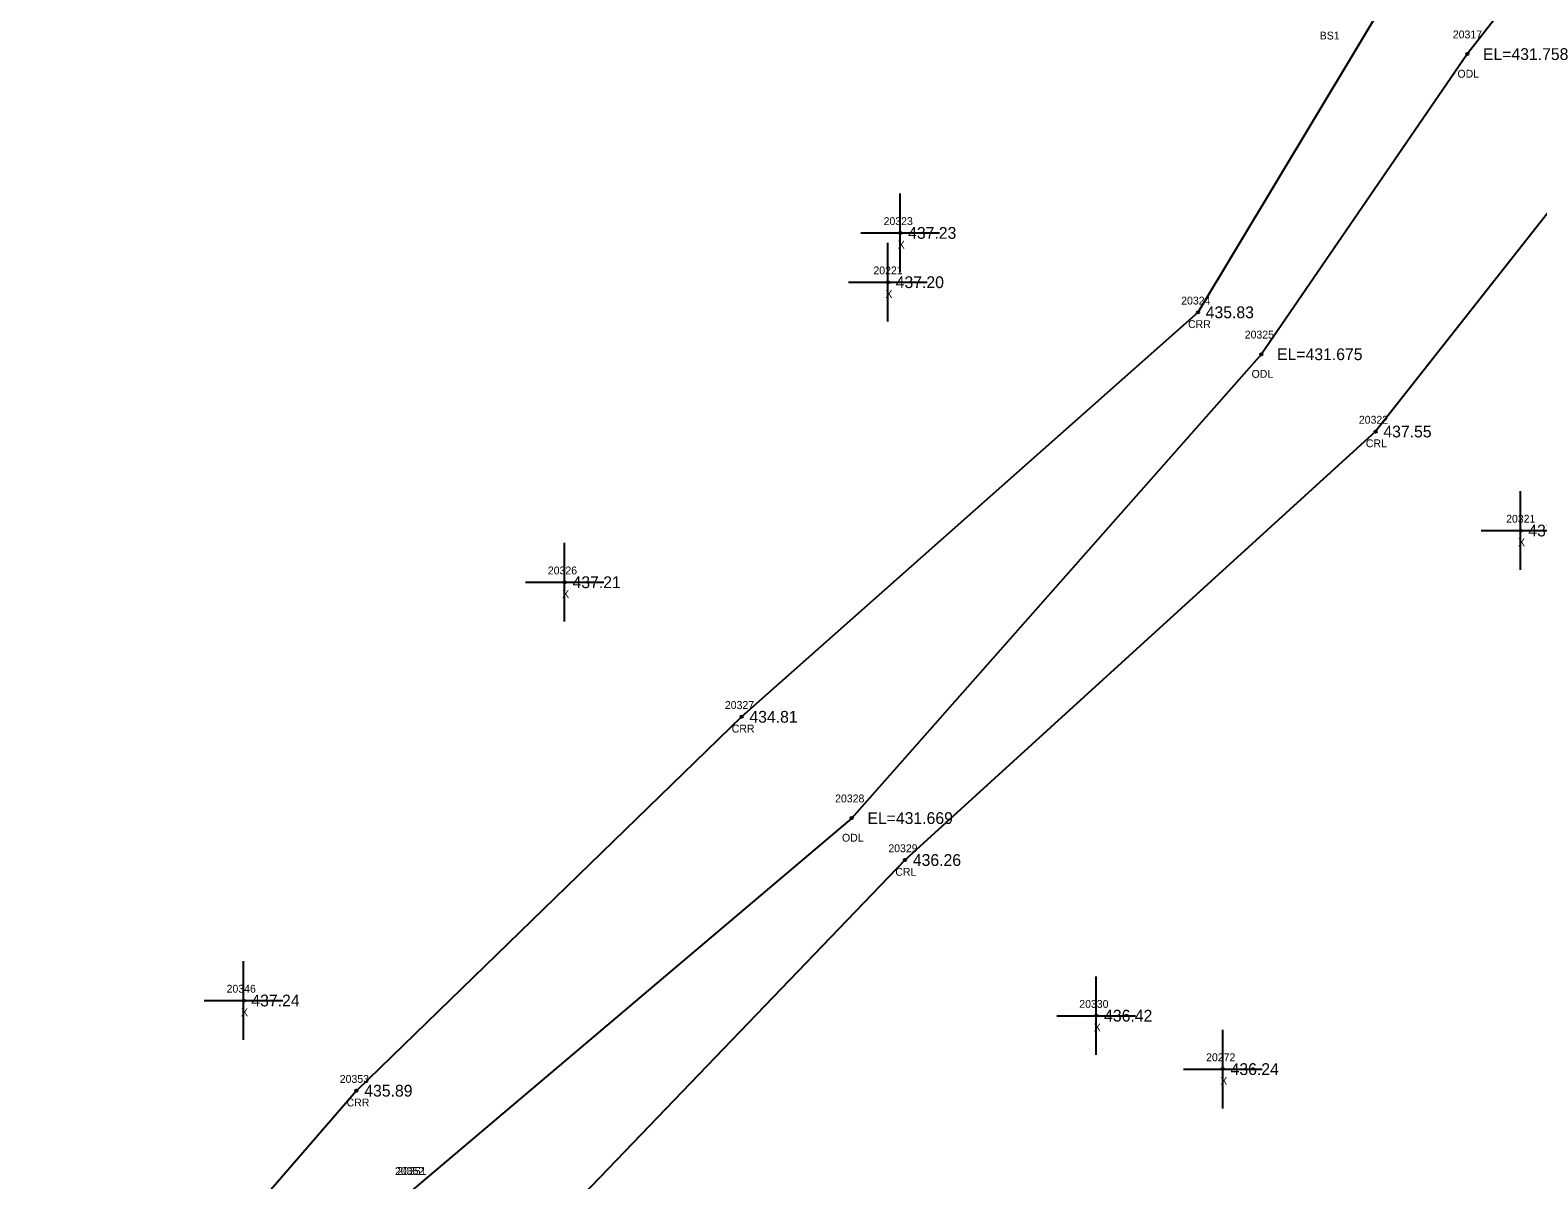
# Model space of a CAD drawing. Extents: x 1797709 to 1799052, y 896018 to 896955.
# Drawn here: x 1798186.8 to 1798378.7, y 896328.3 to 896474.6 of the extents above; entities that cross this region are included whole.
import ezdxf

# ---------------------------------------------------------------- set-up
doc = ezdxf.new("R2010")
doc.units = 0
for name, color, linetype in [('RD_DTM_BkLn_txCode', 7, 'Continuous'), ('RD_EX_H2O', 7, 'Continuous'), ('RD_EX_H2O_txCode', 7, 'Continuous'), ('RD_EX_Misc', 7, 'Continuous'), ('RD_EX_Misc_txCode', 7, 'Continuous'), ('RD_EX_TX_H2O_ELEV', 7, 'Continuous'), ('RD_EX_TX_Misc_ELEV', 7, 'Continuous'), ('RD_SMD_Locator', 7, 'Continuous')]:
    doc.layers.add(name, color=color, linetype=linetype)

msp = doc.modelspace()

# ---------------------------------------------------------------- linework, layer by layer
at = {"layer": 'RD_EX_H2O'}
for points in [[(1798652.43, 896917.58), (1798601.94, 896827.15), (1798558.78, 896718.92), (1798516.66, 896628.32), (1798463.08, 896540.21), (1798439.21, 896521.86), (1798389.85, 896497.35), (1798369.72, 896471.55), (1798343.52, 896433.35), (1798291.39, 896374.31), (1798235.39, 896326.89), (1798184.99, 896269.63), (1798095.18, 896198.01), (1798023.89, 896139.85)], [(1798502.61, 896635.66), (1798452.16, 896551.79), (1798380.86, 896504.02), (1798360.17, 896479.84), (1798335.44, 896438.68), (1798277.37, 896387.2), (1798228.36, 896339.61), (1798175.66, 896278.7), (1798083.83, 896204.11), (1798020.11, 896146.19)], [(1798443.56, 896510.19), (1798406.44, 896491.18), (1798387.57, 896460.96), (1798358.05, 896423.51), (1798298.17, 896368.97), (1798249.86, 896318.72)]]:
    msp.add_lwpolyline(points, dxfattribs=at)
at = {"layer": 'RD_EX_Misc'}
for p, q in [((1798297.57, 896443.79), (1798297.57, 896453.79)), ((1798292.57, 896448.79), (1798302.57, 896448.79)), ((1798295.99, 896437.52), (1798295.99, 896447.52)), ((1798290.99, 896442.52), (1798300.99, 896442.52)), ((1798376.5, 896405.91), (1798376.5, 896415.91)), ((1798371.5, 896410.91), (1798381.5, 896410.91)), ((1798254.86, 896399.33), (1798254.86, 896409.33)), ((1798249.86, 896404.33), (1798259.86, 896404.33)), ((1798213.99, 896346.09), (1798213.99, 896356.09)), ((1798322.51, 896344.16), (1798322.51, 896354.16)), ((1798208.99, 896351.09), (1798218.99, 896351.09)), ((1798317.51, 896349.16), (1798327.51, 896349.16)), ((1798338.61, 896337.36), (1798338.61, 896347.36)), ((1798333.61, 896342.36), (1798343.61, 896342.36))]:
    msp.add_line(p, q, dxfattribs=at)
at = {"layer": 'RD_SMD_Locator'}
for centre in [(1798369.72, 896471.55), (1798297.57, 896448.79), (1798295.99, 896442.52), (1798335.44, 896438.68), (1798343.52, 896433.35), (1798358.05, 896423.51), (1798376.5, 896410.91), (1798254.86, 896404.33), (1798277.37, 896387.2), (1798291.39, 896374.31), (1798298.17, 896368.97), (1798213.99, 896351.09), (1798322.51, 896349.16), (1798338.61, 896342.36), (1798228.36, 896339.61)]:
    msp.add_circle(centre, 0.15, dxfattribs=at)

# ---------------------------------------------------------------- texts
at = {"layer": 'RD_DTM_BkLn_txCode'}
msp.add_text('BS1', height=1, dxfattribs=at).set_placement((1798350.95, 896473.41))
at = {"layer": 'RD_EX_H2O_txCode'}
for s, p in [('20317', (1798367.89, 896473.55)), ('ODL', (1798368.48, 896468.55)), ('20324', (1798333.32, 896439.68)), ('CRR', (1798334.19, 896436.68)), ('20325', (1798341.41, 896435.35)), ('ODL', (1798342.28, 896430.35)), ('20322', (1798355.93, 896424.51)), ('CRL', (1798356.82, 896421.51)), ('20327', (1798275.25, 896388.2)), ('CRR', (1798276.12, 896385.2)), ('20328', (1798289.28, 896376.31)), ('ODL', (1798290.15, 896371.31)), ('20329', (1798296.05, 896369.97)), ('CRL', (1798296.94, 896366.97)), ('20353', (1798226.24, 896340.61)), ('CRR', (1798227.11, 896337.61)), ('20352', (1798233.27, 896328.89)), ('20351', (1798233.55, 896328.89))]:
    msp.add_text(s, height=1, dxfattribs=at).set_placement(p)
at = {"layer": 'RD_EX_Misc_txCode'}
for s, p in [('20323', (1798295.45, 896449.79)), ('X', (1798297.25, 896446.79)), ('20221', (1798294.15, 896443.52)), ('X', (1798295.67, 896440.52)), ('20321', (1798374.67, 896411.91)), ('X', (1798376.19, 896408.91)), ('20326', (1798252.72, 896405.33)), ('X', (1798254.54, 896402.33)), ('20346', (1798211.84, 896352.09)), ('20330', (1798320.35, 896350.16)), ('X', (1798213.67, 896349.09)), ('X', (1798322.19, 896347.16)), ('20272', (1798336.49, 896343.36)), ('X', (1798338.3, 896340.36))]:
    msp.add_text(s, height=1, dxfattribs=at).set_placement(p)
at = {"layer": 'RD_EX_TX_H2O_ELEV'}
for s, p in [('EL=431.758', (1798371.72, 896470.8)), ('435.83', (1798336.44, 896437.93)), ('EL=431.675', (1798345.52, 896432.6)), ('437.55', (1798359.05, 896422.76)), ('434.81', (1798278.37, 896386.45)), ('EL=431.669', (1798293.39, 896373.56)), ('436.26', (1798299.17, 896368.22)), ('435.89', (1798229.36, 896338.86))]:
    msp.add_text(s, height=1.5, dxfattribs=at).set_placement(p)
at = {"layer": 'RD_EX_TX_Misc_ELEV'}
for s, p in [('437.23', (1798298.57, 896448.04)), ('437.20', (1798296.99, 896441.77)), ('437.93', (1798377.5, 896410.16)), ('437.21', (1798255.86, 896403.58)), ('437.24', (1798214.99, 896350.34)), ('436.42', (1798323.51, 896348.41)), ('436.24', (1798339.61, 896341.61))]:
    msp.add_text(s, height=1.5, dxfattribs=at).set_placement(p)

doc.saveas('drawing.dxf')
